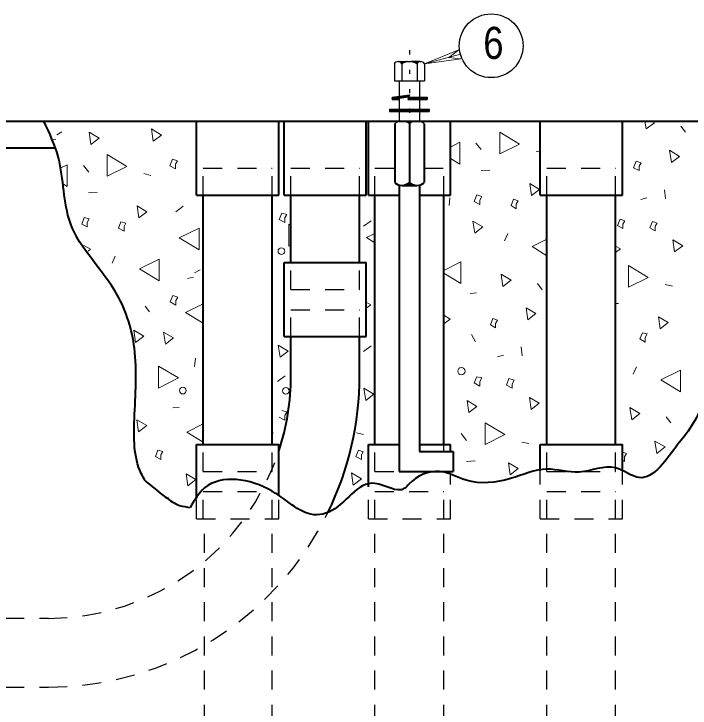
# Model space of a CAD drawing. Extents: x 312583 to 312854, y 144419 to 144597.
# Drawn here: x 312817.2 to 312833.23, y 144530.31 to 144546.77 of the extents above; entities that cross this region are included whole.
import ezdxf

# ---------------------------------------------------------------- set-up
doc = ezdxf.new("R2010")
doc.units = 0
doc.header["$LTSCALE"] = 0.3
doc.linetypes.add('DOTTED', pattern=[1.5, 0.3, -1.2])
doc.linetypes.add('SHORT_DASHED', pattern=[2.7, 1.5, -1.2])
doc.layers.add('1', color=7, linetype='Continuous', lineweight=25)
doc.layers.add('2', color=7, linetype='Continuous', lineweight=13)

msp = doc.modelspace()

# ---------------------------------------------------------------- linework, layer by layer
at = {"layer": '1', "linetype": 'DOTTED'}
msp.add_line((312826.5773, 144545.9033), (312826.5773, 144544.2243), dxfattribs=at)
at = {"layer": '1'}
for p, q in [((312826.217, 144545.5813), (312826.217, 144545.1826)), ((312826.309, 144545.6349), (312826.8456, 144545.6349)), ((312826.3933, 144545.5813), (312826.3933, 144545.1826)), ((312826.7536, 144545.5813), (312826.7536, 144545.1826)), ((312826.93, 144545.5813), (312826.93, 144545.1826)), ((312826.217, 144545.1826), (312826.93, 144545.1826)), ((312826.332, 144545.1826), (312826.332, 144544.2243)), ((312826.815, 144545.1826), (312826.815, 144544.2243)), ((312826.1633, 144544.7916), (312826.1633, 144544.7379)), ((312826.5543, 144544.7916), (312826.9913, 144544.7916)), ((312826.9913, 144544.7916), (312826.9913, 144544.7379)), ((312826.539, 144544.7379), (312826.9913, 144544.7379)), ((312826.102, 144544.5079), (312827.045, 144544.5079)), ((312826.102, 144544.5079), (312826.102, 144544.4543)), ((312826.102, 144544.4926), (312827.045, 144544.4926)), ((312826.102, 144544.4773), (312827.045, 144544.4773)), ((312826.102, 144544.4619), (312827.045, 144544.4619)), ((312826.102, 144544.4543), (312827.045, 144544.4543)), ((312827.045, 144544.5079), (312827.045, 144544.4543)), ((312826.332, 144544.2243), (312826.815, 144544.2243)), ((312826.401, 144544.2243), (312826.746, 144544.2243))]:
    msp.add_line(p, q, dxfattribs=at)
at = {"layer": '1', "lineweight": 40}
for p, q in [((312778.6606, 144544.2243), (312839.994, 144544.2243)), ((312821.525, 144542.4686), (312821.525, 144544.2243)), ((312823.48, 144542.4686), (312823.48, 144544.2243)), ((312823.6026, 144542.4686), (312823.6026, 144544.2243)), ((312825.55, 144542.4686), (312825.55, 144544.2243)), ((312825.6036, 144542.4686), (312825.6036, 144544.2243)), ((312826.2246, 144544.1629), (312826.2246, 144542.7676)), ((312826.5773, 144544.2243), (312826.5773, 144542.6986)), ((312826.9223, 144544.1629), (312826.9223, 144542.7676)), ((312827.551, 144542.4686), (312827.551, 144544.2243)), ((312829.6746, 144542.4686), (312829.6746, 144544.2243)), ((312829.6746, 144542.4686), (312829.6746, 144544.2243)), ((312831.622, 144542.4686), (312831.622, 144544.2243)), ((312794.3773, 144543.5879), (312818.19, 144543.5879)), ((312826.332, 144542.6986), (312826.332, 144535.9213)), ((312826.401, 144542.6986), (312826.746, 144542.6986)), ((312826.815, 144542.6986), (312826.815, 144536.3966)), ((312821.525, 144542.4686), (312823.48, 144542.4686)), ((312821.686, 144536.5576), (312821.686, 144542.4686)), ((312823.319, 144536.5576), (312823.319, 144542.4686)), ((312823.6026, 144542.4686), (312825.55, 144542.4686)), ((312823.7636, 144540.8739), (312823.7636, 144542.4686)), ((312825.389, 144540.8739), (312825.389, 144542.4686)), ((312825.6036, 144542.4686), (312826.332, 144542.4686)), ((312825.757, 144536.5576), (312825.757, 144542.4686)), ((312826.815, 144542.4686), (312827.551, 144542.4686)), ((312827.39, 144536.5576), (312827.39, 144542.4686)), ((312829.6746, 144542.4686), (312831.622, 144542.4686)), ((312829.8356, 144536.5576), (312829.8356, 144542.4686)), ((312831.461, 144536.5576), (312831.461, 144542.4686)), ((312823.6026, 144539.1183), (312823.6026, 144540.8739)), ((312823.6026, 144540.8739), (312825.55, 144540.8739)), ((312825.55, 144539.1183), (312825.55, 144540.8739)), ((312823.6026, 144539.1183), (312825.55, 144539.1183)), ((312823.7636, 144538.1906), (312823.7636, 144539.1183)), ((312825.389, 144538.1906), (312825.389, 144539.1183)), ((312821.525, 144536.5576), (312823.48, 144536.5576)), ((312821.525, 144535.2773), (312821.525, 144536.5576)), ((312823.48, 144535.3693), (312823.48, 144536.5576)), ((312825.6036, 144536.5576), (312826.332, 144536.5576)), ((312825.6036, 144535.5533), (312825.6036, 144536.5576)), ((312826.815, 144536.5576), (312827.551, 144536.5576)), ((312827.551, 144536.3966), (312827.551, 144536.5576)), ((312829.6746, 144536.5576), (312831.622, 144536.5576)), ((312829.6746, 144535.9366), (312829.6746, 144536.5576)), ((312831.622, 144535.9443), (312831.622, 144536.5576)), ((312826.815, 144536.3966), (312827.6123, 144536.3966)), ((312827.6123, 144536.3966), (312827.6123, 144535.9213)), ((312826.332, 144535.9213), (312827.6123, 144535.9213))]:
    msp.add_line(p, q, dxfattribs=at)
at = {"layer": '1', "lineweight": 13}
msp.add_line((312826.9223, 144543.2813), (312826.9376, 144543.2813), dxfattribs=at)
at = {"layer": '1', "linetype": 'SHORT_DASHED'}
for p, q in [((312821.686, 144543.1126), (312823.319, 144543.1126)), ((312821.686, 144542.4686), (312821.686, 144543.1126)), ((312823.319, 144542.4686), (312823.319, 144543.1126)), ((312823.7636, 144543.1126), (312825.389, 144543.1126)), ((312823.7636, 144542.4686), (312823.7636, 144543.1126)), ((312825.389, 144542.4686), (312825.389, 144543.1126)), ((312825.757, 144542.4686), (312825.757, 144543.1126)), ((312825.757, 144543.1126), (312826.2246, 144543.1126)), ((312826.9223, 144543.1126), (312827.39, 144543.1126)), ((312827.39, 144542.4686), (312827.39, 144543.1126)), ((312829.8356, 144543.1126), (312831.461, 144543.1126)), ((312829.8356, 144542.4686), (312829.8356, 144543.1126)), ((312831.461, 144542.4686), (312831.461, 144543.1126)), ((312823.7636, 144540.2376), (312823.7636, 144540.8739)), ((312825.389, 144540.2376), (312825.389, 144540.8739)), ((312823.7636, 144540.2376), (312825.389, 144540.2376)), ((312823.7636, 144539.7546), (312825.389, 144539.7546)), ((312823.7636, 144539.1183), (312823.7636, 144539.7546)), ((312825.389, 144539.1183), (312825.389, 144539.7546)), ((312821.686, 144535.9213), (312821.686, 144536.5576)), ((312823.319, 144535.9213), (312823.319, 144536.5576)), ((312825.757, 144535.9213), (312825.757, 144536.5576)), ((312827.39, 144536.3966), (312827.39, 144536.5576)), ((312829.8356, 144535.9213), (312829.8356, 144536.5576)), ((312831.461, 144535.9213), (312831.461, 144536.5576)), ((312821.686, 144535.9213), (312823.319, 144535.9213)), ((312825.757, 144535.9213), (312826.332, 144535.9213)), ((312826.815, 144535.9213), (312827.39, 144535.9213)), ((312829.6746, 144534.8019), (312829.6746, 144535.9366)), ((312829.8356, 144535.9213), (312831.461, 144535.9213)), ((312831.622, 144534.8019), (312831.622, 144535.9443)), ((312827.551, 144534.8019), (312827.551, 144535.8369)), ((312825.6036, 144534.8019), (312825.6036, 144535.5379)), ((312821.686, 144535.4459), (312823.319, 144535.4459)), ((312821.686, 144534.8019), (312821.686, 144535.4459)), ((312823.319, 144534.8019), (312823.319, 144535.4459)), ((312823.48, 144534.8019), (312823.48, 144535.3693)), ((312825.757, 144534.8019), (312825.757, 144535.4459)), ((312825.757, 144535.4459), (312827.39, 144535.4459)), ((312827.39, 144534.8019), (312827.39, 144535.4459)), ((312829.8356, 144535.4459), (312831.461, 144535.4459)), ((312829.8356, 144534.8019), (312829.8356, 144535.4459)), ((312831.461, 144534.8019), (312831.461, 144535.4459)), ((312821.525, 144534.8019), (312821.525, 144535.2773)), ((312821.525, 144534.8019), (312823.48, 144534.8019)), ((312821.7166, 144523.4629), (312821.7166, 144534.8019)), ((312823.319, 144523.4629), (312823.319, 144534.8019)), ((312825.6036, 144534.8019), (312827.551, 144534.8019)), ((312825.757, 144523.4629), (312825.757, 144534.8019)), ((312827.39, 144523.4629), (312827.39, 144534.8019)), ((312829.6746, 144534.8019), (312831.622, 144534.8019)), ((312829.8356, 144523.4629), (312829.8356, 144534.8019)), ((312831.461, 144523.4629), (312831.461, 144534.8019)), ((312816.1813, 144532.4406), (312818.0136, 144532.4406)), ((312816.1813, 144530.8076), (312818.0136, 144530.8076))]:
    msp.add_line(p, q, dxfattribs=at)
at = {"layer": '1'}
for points in [[(312826.332, 144545.6349), (312826.5313, 144545.6349), (312826.493, 144545.6273), (312826.47, 144545.6196), (312826.4316, 144545.6119), (312826.3933, 144545.5813), (312826.3856, 144545.6043), (312826.3626, 144545.6196), (312826.3396, 144545.6349), (312826.516, 144545.6349), (312826.4623, 144545.6196), (312826.424, 144545.6043), (312826.401, 144545.5889), (312826.3703, 144545.6196), (312826.3473, 144545.6273), (312826.493, 144545.6349), (312826.4393, 144545.6196), (312826.401, 144545.5966), (312826.3626, 144545.6273), (312826.4776, 144545.6273), (312826.3933, 144545.5966), (312826.3626, 144545.6273), (312826.4623, 144545.6273), (312826.3933, 144545.6043), (312826.3703, 144545.6273), (312826.447, 144545.6273), (312826.3933, 144545.6043), (312826.3856, 144545.6196), (312826.4316, 144545.6196), (312826.401, 144545.6119), (312826.3933, 144545.6196), (312826.4086, 144545.6196), (312826.401, 144545.6119)], [(312826.8226, 144545.6349), (312826.6233, 144545.6349), (312826.654, 144545.6273), (312826.677, 144545.6196), (312826.7153, 144545.6119), (312826.7536, 144545.5813), (312826.769, 144545.6043), (312826.7843, 144545.6196), (312826.815, 144545.6349), (312826.6386, 144545.6349), (312826.6846, 144545.6196), (312826.723, 144545.6043), (312826.7536, 144545.5889), (312826.7766, 144545.6196), (312826.7996, 144545.6273), (312826.6616, 144545.6349), (312826.7076, 144545.6196), (312826.7536, 144545.5966), (312826.792, 144545.6273), (312826.677, 144545.6273), (312826.7536, 144545.5966), (312826.7843, 144545.6273), (312826.6846, 144545.6273), (312826.7536, 144545.6043), (312826.7766, 144545.6273), (312826.7, 144545.6273), (312826.7536, 144545.6043), (312826.769, 144545.6196), (312826.723, 144545.6196), (312826.7536, 144545.6119), (312826.7613, 144545.6196), (312826.7383, 144545.6196), (312826.7536, 144545.6119)], [(312826.1633, 144544.7916), (312826.5773, 144544.8453), (312826.539, 144544.7379)], [(312826.332, 144544.7379), (312826.1633, 144544.7456), (312826.171, 144544.7839), (312826.562, 144544.8376), (312826.5466, 144544.7993), (312826.332, 144544.7686), (312826.332, 144544.7456), (312826.171, 144544.7456), (312826.171, 144544.7763), (312826.5543, 144544.8299), (312826.5466, 144544.7993), (312826.3243, 144544.7686), (312826.3166, 144544.7456), (312826.1786, 144544.7533), (312826.1786, 144544.7686), (312826.539, 144544.8223), (312826.539, 144544.8146), (312826.3243, 144544.7686), (312826.309, 144544.7686), (312826.2706, 144544.7533), (312826.1863, 144544.7609), (312826.5313, 144544.8146), (312826.24, 144544.7609)], [(312826.5543, 144544.7916), (312826.1633, 144544.7379), (312826.332, 144544.7379)], [(312826.5466, 144544.7379), (312826.9836, 144544.7379), (312826.9836, 144544.7839), (312826.562, 144544.7839), (312826.5466, 144544.7456), (312826.976, 144544.7456), (312826.976, 144544.7763), (312826.5696, 144544.7763), (312826.562, 144544.7533), (312826.9683, 144544.7533), (312826.9606, 144544.7686), (312826.9606, 144544.7686), (312826.5696, 144544.7686), (312826.5696, 144544.7609), (312826.9606, 144544.7609)], [(312826.447, 144544.2243), (312826.7076, 144544.2243), (312826.677, 144544.2166), (312826.6463, 144544.2089), (312826.6156, 144544.2013), (312826.6003, 144544.1859), (312826.5773, 144544.1706), (312826.5773, 144544.1706), (312826.5236, 144544.2013), (312826.4853, 144544.2166), (312826.4623, 144544.2243), (312826.6846, 144544.2243), (312826.6693, 144544.2243), (312826.6463, 144544.2166), (312826.6233, 144544.2089), (312826.5926, 144544.1936), (312826.585, 144544.1859), (312826.5773, 144544.1706), (312826.5313, 144544.2013), (312826.4853, 144544.2166), (312826.654, 144544.2243), (312826.6156, 144544.2089), (312826.5773, 144544.1859), (312826.5006, 144544.2166), (312826.6386, 144544.2166), (312826.5773, 144544.1783), (312826.516, 144544.2166), (312826.6233, 144544.2166), (312826.5773, 144544.1936), (312826.539, 144544.2089), (312826.608, 144544.2089), (312826.5773, 144544.2013), (312826.539, 144544.2089), (312826.562, 144544.1936), (312826.5696, 144544.2089), (312826.5696, 144544.1859), (312826.585, 144544.2013), (312826.6003, 144544.2013), (312826.608, 144544.2089)]]:
    msp.add_lwpolyline(points, dxfattribs=at)
at = {"layer": '1', "lineweight": 40}
msp.add_lwpolyline([(312826.447, 144542.7063), (312826.7076, 144542.6986), (312826.677, 144542.7063), (312826.6463, 144542.7139), (312826.6156, 144542.7293), (312826.6003, 144542.7369), (312826.5773, 144542.7523), (312826.5773, 144542.7599), (312826.5236, 144542.7293), (312826.4853, 144542.7139), (312826.4623, 144542.7063), (312826.6846, 144542.7063), (312826.6693, 144542.7063), (312826.6463, 144542.7139), (312826.6233, 144542.7216), (312826.5926, 144542.7369), (312826.585, 144542.7446), (312826.5773, 144542.7523), (312826.5313, 144542.7216), (312826.4853, 144542.7063), (312826.654, 144542.7063), (312826.6156, 144542.7216), (312826.5773, 144542.7446), (312826.5006, 144542.7139), (312826.6386, 144542.7063), (312826.5773, 144542.7446), (312826.516, 144542.7139), (312826.6233, 144542.7139), (312826.5773, 144542.7369), (312826.539, 144542.7139), (312826.608, 144542.7139), (312826.5773, 144542.7293), (312826.539, 144542.7216), (312826.562, 144542.7369), (312826.5696, 144542.7216), (312826.5696, 144542.7446), (312826.585, 144542.7216), (312826.6003, 144542.7216), (312826.608, 144542.7216)], dxfattribs=at)
at = {"layer": '1'}
for centre, radius, start, end in [((312826.3055, 144545.5372), 0.0993, 25.60064, 154.39936), ((312826.5741, 144545.3239), 0.3126, 55.04559, 124.95441), ((312826.8428, 144545.5372), 0.0993, 25.60064, 154.39936), ((312826.3993, 144543.9547), 0.272, 50.00693, 129.99306), ((312826.7489, 144543.9547), 0.272, 50.00694, 129.99307)]:
    msp.add_arc(centre, radius, start, end, dxfattribs=at)
at = {"layer": '1', "lineweight": 40}
for centre, radius, start, end in [((312826.3993, 144542.9721), 0.272, 230.00694, 309.99307), ((312826.7489, 144542.9721), 0.272, 230.00693, 309.99306), ((312818.013, 144538.1893), 5.75, 341.8604, 0), ((312818.013, 144538.1893), 7.3792, 333.96299, 0)]:
    msp.add_arc(centre, radius, start, end, dxfattribs=at)
at = {"layer": '1', "linetype": 'SHORT_DASHED'}
for radius, end in [(5.75, 342.27769), (7.3792, 333.99012)]:
    msp.add_arc((312818.013, 144538.1893), radius, 270, end, dxfattribs=at)
at = {"layer": '1', "lineweight": 40}
for points in [[(312820.306, 144535.6989), (312820.214, 144535.8753), (312820.053, 144537.1709), (312820.053, 144538.8423), (312819.6466, 144540.1073), (312818.535, 144541.8093), (312818.2513, 144543.3579), (312817.9063, 144544.2243)], [(312833.8223, 144544.2243), (312834.3283, 144543.3579), (312834.9263, 144542.4763), (312834.5813, 144541.4029), (312834.014, 144540.9583), (312833.761, 144540.0383), (312833.6306, 144537.8303), (312833.094, 144536.7569), (312832.9406, 144536.5653), (312832.0206, 144535.7756), (312831.461, 144536.0056), (312830.6023, 144535.9059), (312829.8356, 144535.9749), (312828.9693, 144535.7526), (312827.919, 144535.7143), (312827.2903, 144535.9213), (312826.562, 144535.6223), (312826.4623, 144535.5226), (312825.757, 144535.6376), (312824.6606, 144534.9553), (312824.377, 144534.8939), (312823.319, 144535.4536), (312821.7166, 144535.5303), (312821.3793, 144535.0703)], [(312820.306, 144535.6989), (312820.789, 144535.3156), (312821.1263, 144535.1163), (312821.3793, 144535.0703)]]:
    msp.add_spline(points, degree=3, dxfattribs=at)
at = {"layer": '2'}
for p, q in [((312826.93, 144545.5813), (312827.7426, 144545.9109)), ((312827.7426, 144545.9109), (312827.505, 144545.7346)), ((312827.781, 144545.8113), (312826.93, 144545.5813)), ((312827.7963, 144545.7039), (312827.505, 144545.7346)), ((312826.93, 144545.5813), (312827.7963, 144545.7039)), ((312824.2543, 144544.2089), (312824.2773, 144544.2243)), ((312824.2543, 144544.2243), (312824.2543, 144544.2089)), ((312828.3253, 144544.2089), (312828.356, 144544.2243)), ((312828.3253, 144544.2243), (312828.3253, 144544.2089)), ((312832.1586, 144544.2243), (312832.1893, 144544.0403)), ((312833.0096, 144544.1016), (312833.117, 144543.9636)), ((312818.213, 144543.9023), (312818.3356, 144543.9713)), ((312818.098, 144543.7796), (312818.19, 144543.7949)), ((312828.149, 144543.7029), (312828.2716, 144543.5496)), ((312829.5826, 144543.5113), (312829.6746, 144543.4883)), ((312827.551, 144543.3349), (312827.7656, 144543.2046)), ((312818.8493, 144543.1739), (312818.972, 144543.0129)), ((312820.2753, 144542.9823), (312820.444, 144542.9363)), ((312828.2716, 144543.0513), (312828.4786, 144543.0589)), ((312818.374, 144542.7293), (312818.4583, 144542.6756)), ((312818.9643, 144542.5223), (312819.1713, 144542.5299)), ((312832.6186, 144542.5989), (312832.6416, 144542.3919)), ((312827.5126, 144542.2233), (312827.5356, 144542.4073)), ((312832.059, 144542.3689), (312832.2046, 144542.4073)), ((312821.2106, 144542.2079), (312821.0343, 144542.0776)), ((312823.7636, 144541.7556), (312823.7176, 144541.7863)), ((312825.665, 144541.8629), (312825.4886, 144541.7326)), ((312828.908, 144541.5639), (312828.8313, 144541.3876)), ((312819.6006, 144541.0273), (312819.524, 144540.8586)), ((312821.479, 144540.6286), (312821.6093, 144540.6976)), ((312821.3103, 144540.4983), (312821.456, 144540.5289)), ((312827.39, 144540.6209), (312827.7963, 144540.3756)), ((312829.6133, 144540.3756), (312829.7206, 144540.2299)), ((312832.634, 144540.3526), (312832.8103, 144540.3143)), ((312828.011, 144540.1379), (312828.1643, 144540.1533)), ((312820.306, 144539.8389), (312820.4133, 144539.7009)), ((312831.461, 144539.9003), (312831.53, 144539.9003)), ((312828.0493, 144539.1643), (312828.1413, 144538.9956)), ((312825.665, 144538.8959), (312825.4886, 144538.7656)), ((312829.2223, 144538.8729), (312829.2453, 144538.6583)), ((312828.6626, 144538.6353), (312828.8083, 144538.6813)), ((312821.479, 144538.4129), (312821.502, 144538.6046)), ((312831.9593, 144538.3976), (312831.8826, 144538.2289)), ((312823.6256, 144538.1906), (312823.4493, 144538.0526)), ((312820.9653, 144537.4316), (312821.111, 144537.4393)), ((312823.664, 144537.3319), (312823.549, 144537.3626)), ((312823.618, 144537.2476), (312823.664, 144537.3243)), ((312832.6646, 144537.2169), (312832.772, 144537.0713)), ((312823.3496, 144536.8336), (312823.319, 144536.8183)), ((312825.32, 144536.8336), (312825.4886, 144536.7953)), ((312827.804, 144536.8183), (312827.9266, 144536.6573)), ((312829.2376, 144536.6189), (312829.4063, 144536.5806)), ((312827.9266, 144536.1589), (312828.1336, 144536.1743)), ((312820.8656, 144535.3156), (312820.8273, 144535.2926))]:
    msp.add_line(p, q, dxfattribs=at)
for points in [[(312832.1893, 144544.0403), (312832.381, 144544.1859), (312832.312, 144544.2243)], [(312827.7656, 144543.2046), (312827.7656, 144543.7259), (312827.551, 144543.6109)], [(312818.4583, 144542.6756), (312818.4583, 144543.1893), (312818.3126, 144543.1203)], [(312823.7176, 144541.7863), (312823.7176, 144541.2649), (312823.7636, 144541.2879)], [(312825.757, 144541.5639), (312825.5576, 144541.4643), (312825.757, 144541.3416)], [(312829.8356, 144541.4259), (312829.483, 144541.2496), (312829.8356, 144541.0349)], [(312818.9566, 144541.1423), (312819.0103, 144541.1883), (312818.857, 144541.2803)], [(312831.461, 144541.1116), (312831.576, 144541.1959), (312831.461, 144541.2573)], [(312827.7963, 144540.3756), (312827.7963, 144540.8893), (312827.39, 144540.6823)], [(312821.686, 144539.8926), (312821.2643, 144539.6856), (312821.686, 144539.4326)], [(312825.55, 144539.7929), (312825.6573, 144539.8696), (312825.55, 144539.9309)], [(312827.39, 144539.4173), (312827.5433, 144539.5323), (312827.39, 144539.6243)], [(312823.7636, 144538.4053), (312823.7483, 144538.4129), (312823.7636, 144538.3056)], [(312823.4876, 144537.2093), (312823.618, 144537.1403), (312823.618, 144537.2476)], [(312821.686, 144537.0483), (312821.295, 144536.8489), (312821.686, 144536.6189)], [(312831.6756, 144536.2663), (312831.7216, 144536.3506), (312831.622, 144536.3813)], [(312831.622, 144536.1896), (312831.6756, 144536.1589), (312831.6756, 144536.2663)]]:
    msp.add_lwpolyline(points, dxfattribs=at)
for points in [[(312819.018, 144543.6723), (312819.2173, 144543.8179), (312818.9796, 144543.9636)], [(312820.4976, 144543.7489), (312820.697, 144543.8946), (312820.4593, 144544.0403)], [(312828.7163, 144543.9636), (312828.7163, 144543.4499), (312829.184, 144543.6799)], [(312819.409, 144543.4346), (312819.409, 144542.9209), (312819.8766, 144543.1509)], [(312832.7873, 144543.2429), (312832.979, 144543.3886), (312832.7413, 144543.5343)], [(312821.0266, 144543.2046), (312821.0726, 144543.2813), (312820.9576, 144543.3196), (312820.8963, 144543.1663), (312821.0266, 144543.0973)], [(312832.0206, 144543.1586), (312832.0666, 144543.2353), (312831.9516, 144543.2736), (312831.8903, 144543.1203), (312832.0206, 144543.0513)], [(312829.4676, 144542.4609), (312829.6593, 144542.6066), (312829.4293, 144542.7446)], [(312828.241, 144542.3536), (312828.287, 144542.4379), (312828.172, 144542.4763), (312828.1106, 144542.3229), (312828.241, 144542.2463)], [(312829.1073, 144542.2539), (312829.1533, 144542.3383), (312829.0383, 144542.3766), (312828.9846, 144542.2233), (312829.1073, 144542.1466)], [(312820.1603, 144541.9319), (312820.352, 144542.0776), (312820.122, 144542.2156)], [(312823.618, 144541.9319), (312823.664, 144542.0086), (312823.549, 144542.0469), (312823.4876, 144541.8936), (312823.618, 144541.8246)], [(312818.9336, 144541.8246), (312818.9796, 144541.9089), (312818.8646, 144541.9396), (312818.8033, 144541.7863), (312818.9336, 144541.7173)], [(312819.8076, 144541.7249), (312819.8536, 144541.8093), (312819.731, 144541.8399), (312819.6773, 144541.6866), (312819.8076, 144541.6176)], [(312828.126, 144541.5716), (312828.3176, 144541.7173), (312828.08, 144541.8553)], [(312831.6373, 144541.7863), (312831.6833, 144541.8629), (312831.5683, 144541.9013), (312831.507, 144541.7479), (312831.6373, 144541.6789)], [(312832.404, 144541.7326), (312832.45, 144541.8093), (312832.335, 144541.8476), (312832.2736, 144541.6943), (312832.404, 144541.6253)], [(312821.5863, 144541.1729), (312821.5863, 144541.6866), (312821.1186, 144541.4566)], [(312832.8563, 144541.1269), (312833.0556, 144541.2726), (312832.818, 144541.4106)], [(312820.6433, 144540.4369), (312820.6433, 144540.9506), (312820.1756, 144540.7206)], [(312831.7676, 144540.8049), (312831.7676, 144540.2913), (312832.2353, 144540.5213)], [(312828.7853, 144540.3066), (312828.9846, 144540.4523), (312828.747, 144540.5979)], [(312821.0343, 144539.9693), (312821.0803, 144540.0536), (312820.9653, 144540.0919), (312820.904, 144539.9386), (312821.0343, 144539.8619)], [(312829.3833, 144539.5169), (312829.575, 144539.6626), (312829.345, 144539.8006)], [(312828.6166, 144539.4249), (312828.6626, 144539.5093), (312828.5476, 144539.5476), (312828.494, 144539.3943), (312828.6166, 144539.3253)], [(312832.519, 144539.3023), (312832.7106, 144539.4479), (312832.4806, 144539.5859)], [(312820.076, 144538.9803), (312820.2753, 144539.1259), (312820.0376, 144539.2716)], [(312820.789, 144538.9419), (312820.9806, 144539.0876), (312820.743, 144539.2256)], [(312832.1663, 144539.0953), (312832.2123, 144539.1796), (312832.0973, 144539.2103), (312832.036, 144539.0646), (312832.1663, 144538.9879)], [(312823.5106, 144538.6276), (312823.7023, 144538.7733), (312823.4646, 144538.9113)], [(312820.628, 144538.4206), (312820.628, 144537.8993), (312821.0956, 144538.1369)], [(312828.241, 144538.0526), (312828.287, 144538.1369), (312828.172, 144538.1676), (312828.1106, 144538.0219), (312828.241, 144537.9453)], [(312833.002, 144537.8073), (312833.002, 144538.3209), (312832.5343, 144538.0909)], [(312829.0076, 144537.9989), (312829.0536, 144538.0833), (312828.931, 144538.1216), (312828.8773, 144537.9683), (312829.0076, 144537.8993)], [(312825.5423, 144537.6003), (312825.734, 144537.7536), (312825.4963, 144537.8916)], [(312829.46, 144537.3933), (312829.6516, 144537.5389), (312829.4216, 144537.6769)], [(312827.9803, 144537.3166), (312828.172, 144537.4623), (312827.942, 144537.6003)], [(312831.8443, 144537.1479), (312832.036, 144537.2936), (312831.7983, 144537.4393)], [(312820.1526, 144536.8643), (312820.352, 144537.0099), (312820.1143, 144537.1479)], [(312828.3713, 144537.0713), (312828.3713, 144536.5576), (312828.839, 144536.7953)], [(312832.4423, 144536.3506), (312832.634, 144536.5039), (312832.3963, 144536.6419)], [(312820.6816, 144536.3123), (312820.7276, 144536.3966), (312820.6126, 144536.4273), (312820.5513, 144536.2739), (312820.6816, 144536.2049)], [(312825.435, 144536.3123), (312825.481, 144536.3889), (312825.366, 144536.4273), (312825.3046, 144536.2739), (312825.435, 144536.2049)], [(312828.9616, 144535.8446), (312829.1533, 144535.9903), (312828.9233, 144536.1283)], [(312821.318, 144535.5839), (312821.5096, 144535.7296), (312821.2796, 144535.8676)], [(312825.2433, 144535.5993), (312825.435, 144535.7449), (312825.1973, 144535.8906)]]:
    msp.add_lwpolyline(points, close=True, dxfattribs=at)
at = {"layer": '2', "lineweight": 25}
msp.add_circle((312828.5125, 144546.0106), 0.7557, dxfattribs=at)
at = {"layer": '2'}
for centre, radius in [((312823.5379, 144541.1442), 0.0784), ((312827.8067, 144538.2983), 0.0865), ((312821.2011, 144537.8373), 0.0784), ((312823.6439, 144537.8341), 0.0784)]:
    msp.add_circle(centre, radius, dxfattribs=at)

# ---------------------------------------------------------------- texts
at = {"layer": '2', "width": 0.85}
msp.add_text('6', height=0.76, dxfattribs=at).set_placement((312828.325, 144545.6992))

doc.saveas('drawing.dxf')
